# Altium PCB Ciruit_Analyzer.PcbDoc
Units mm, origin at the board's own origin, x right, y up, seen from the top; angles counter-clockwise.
Board outline 50.93 x 49.66 mm, 2 copper layers (Top Layer, Bottom Layer); 10 components, 6 nets, 28 pads, 0 vias.
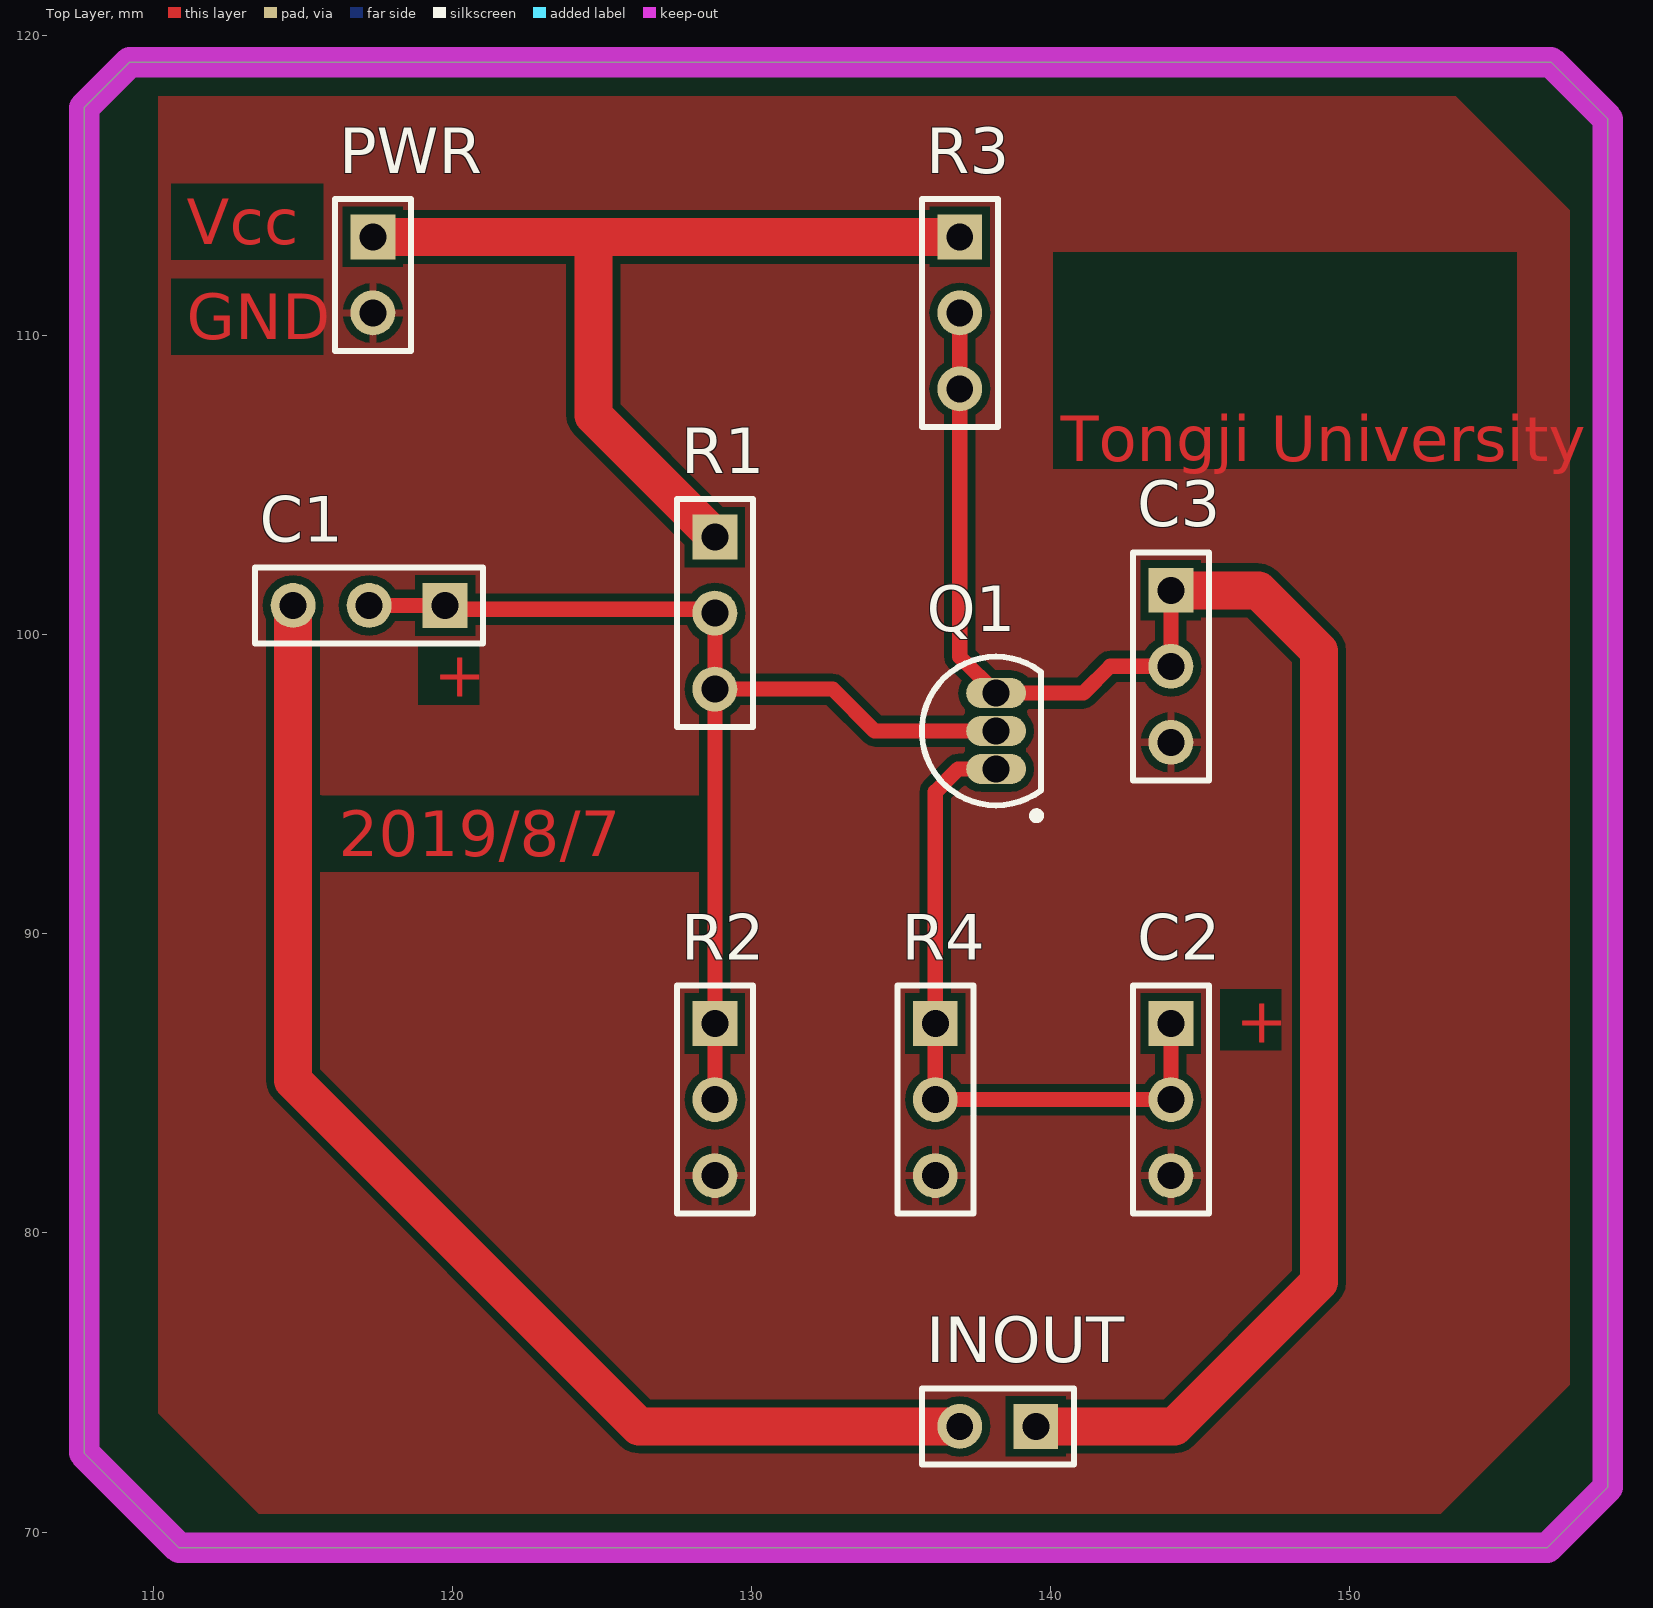
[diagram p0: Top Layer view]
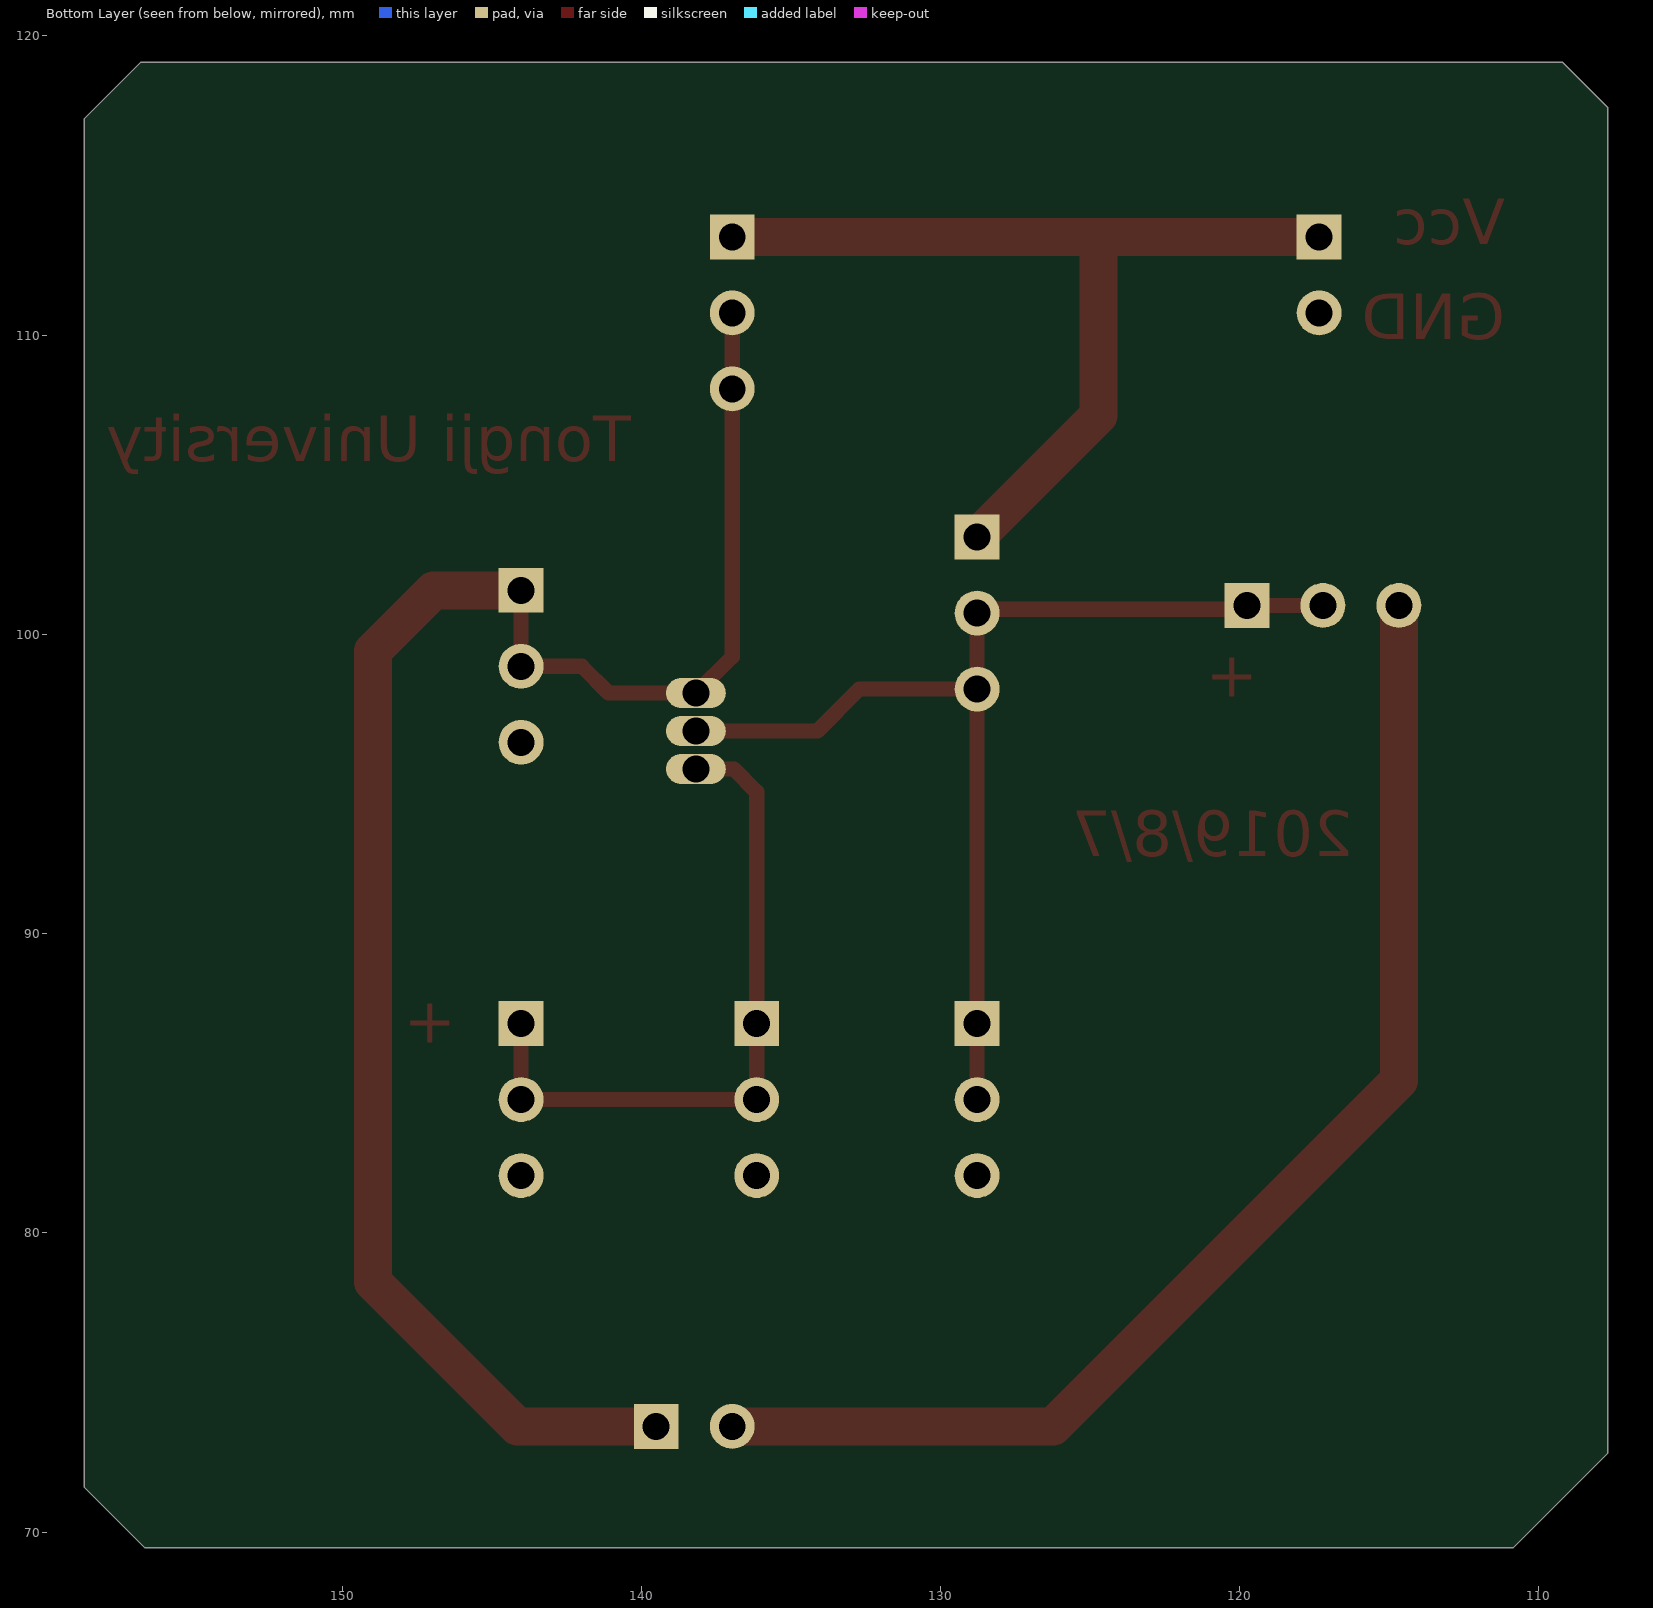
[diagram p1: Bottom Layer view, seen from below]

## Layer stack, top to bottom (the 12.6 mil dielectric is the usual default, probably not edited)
Top Solder: solder mask 0.0102, Solder Resist, Dk 3.5
Top Layer: signal copper 0.0356
Dielectric 1: dielectric 0.32, FR-4, Dk 4.8
Bottom Layer: signal copper 0.0356
Bottom Solder: solder mask 0.0102, Solder Resist, Dk 3.5

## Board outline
107.696,72.644 107.696,117.602 109.22,119.126 156.718,119.126 158.623,117.221 158.623,71.501 156.591,69.469 110.871,69.469

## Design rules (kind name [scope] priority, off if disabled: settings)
Clearance [All] p1: gap=0.254 ignorepadtopadclearanceinfootprint=FALSE except(0: Arc-Hole Track-Hole SMDPad-Hole THPad-Hole Via-Hole Fill-Hole Poly-Hole Region-Hole Text-Hole)
PolygonConnect [All] p1: connectstyle=Relief reliefconductorwidth=0.254 reliefentries=4 polygonreliefangle="90 Angle" airgapwidth=0.254
RoutingVias [All] p1: holewidth=0.711 width=1.27 viastyle="Through Hole" minholewidth=0.711 minwidth=1.27 maxholewidth=0.711 maxwidth=1.27
SolderMaskExpansion [All] p1: expansion=0.102
Width [All] p1: maxlimit=1.27 minlimit=0.254 preferedwidth=0.508 minimp=50.000000 maximp=50.000000 favimp=50.000000
30 further rules are at their usual default settings.

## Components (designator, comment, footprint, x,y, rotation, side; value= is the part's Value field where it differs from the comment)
C1 "10u" HDR1X3 119.761,100.965 r180 top
C2 "47uf" HDR1X3 144.018,86.995 r270 top
C3 "470pf" HDR1X3 144.018,101.473 r270 top
INOUT "" HDR1X2 139.502,73.533 r180 top
PWR "" HDR1X2 117.348,113.284 r270 top
Q1 "9013" TO-92A 138.176,96.769 r0 top
R1 "R1 43K" HDR1X3 128.778,103.251 r270 top
R2 "R2 15K" HDR1X3 128.778,86.995 r270 top
R3 "R3 2K" HDR1X3 136.962,113.284 r270 top
R4 "R4 1K" HDR1X3 136.144,86.995 r270 top

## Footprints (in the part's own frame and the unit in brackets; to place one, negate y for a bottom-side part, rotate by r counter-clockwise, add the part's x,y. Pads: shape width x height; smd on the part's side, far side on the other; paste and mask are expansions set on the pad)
HDR1X2 [mm] "Connector; Header; 2 Position"
  rect 1.5x1.5 hole 0.9: 1(0,0)
  round 1.5 hole 0.9: 2(2.54,0)
  silkscreen extent -1.27,-1.27 3.81,1.27
HDR1X3 [mm] "Connector; Header; 3 Position"
  rect 1.5x1.5 hole 0.9: 1(0,0)
  round 1.5 hole 0.9: 2(2.54,0) 3(5.08,0)
  silkscreen extent -1.27,-1.27 6.35,1.27
TO-92A [mm] "TO, Flat Index; 3 In-Line, Axial Leads; Body Dia. 4.5mm; Leads 0.51 x 0.48 mm (max)"
  oval 2x1 hole 0.9: 1(0,-1.27) 2(0,0) 3(0,1.27)
  silkscreen extent -2.48,-2.95 1.5,2.48, body extent -2.48,-2.5 1.5,2.5, height 6.86

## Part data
C1 C2 C3 R1 R2 R3 R4: library part "Header 3", "Header, 3-Pin"
INOUT PWR: library part "Header 2", "Header, 2-Pin"
Q1: library part 2N3904, "NPN General Purpose Amplifier"

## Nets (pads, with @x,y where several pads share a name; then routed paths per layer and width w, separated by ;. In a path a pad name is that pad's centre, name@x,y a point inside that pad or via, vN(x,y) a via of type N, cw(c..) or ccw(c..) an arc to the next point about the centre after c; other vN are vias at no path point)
DC+12V: PWR.1 R1.1 R3.1 | length 31.3
  Top Layer w1.27: PWR.1 124.714,113.284 ; R1.1 124.714,107.315 124.714,113.284 ; R3.1 124.714,113.284
GND: C2.3 C3.3 PWR.2 R2.3 R4.3
NetC1_1: C1.1 C1.2 Q1.2 R1.2 R1.3 R2.1 R2.2 | length 37.9
  Top Layer w0.508: C1.2 C1.1 119.888,100.838 128.651,100.838 R1.2 R1.3 ; R2.2 R2.1 R1.3 ; Q1.2 134.117,96.769 132.715,98.171 R1.3
NetC2_1: C2.1 C2.2 Q1.1 R4.1 R4.2 | length 23
  Top Layer w0.508: Q1.1 136.906,95.499 136.144,94.737 R4.1 R4.2 C2.2 C2.1
Ui: C1.3 INOUT.2 | length 42.9
  Top Layer w1.27: C1.3 114.681,85.09 126.238,73.533 INOUT.2
Uo: C3.1 C3.2 INOUT.1 Q1.3 R3.2 R3.3 | length 60.3
  Top Layer w0.508: R3.2 R3.3 136.962,99.253 Q1.3 141.097,98.039 141.991,98.933 C3.2 C3.1
  Top Layer w1.27: INOUT.1 144.145,73.533 148.971,78.359 148.971,99.441 146.939,101.473 C3.1

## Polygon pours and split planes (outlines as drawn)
GND on Top Layer "GND_L01_P002" (solid, remove dead copper, pour order 2): 110.172,117.983 153.543,117.983 157.353,114.173 157.353,74.93 153.035,70.612 113.538,70.612 110.172,73.977

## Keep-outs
Top Layer:
  the board outline again, w1.016

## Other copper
Top Layer:
  text "Vcc" at 111.125,113.03 h1.52
  text "GND" at 111.125,109.855 h1.52
  text "Tongji University" at 140.335,105.791 h1.52
  text "+" at 119.38,97.909 h1.52
  text "2019/8/7" at 116.205,92.583 h1.52
  text "+" at 146.177,86.36 h1.52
